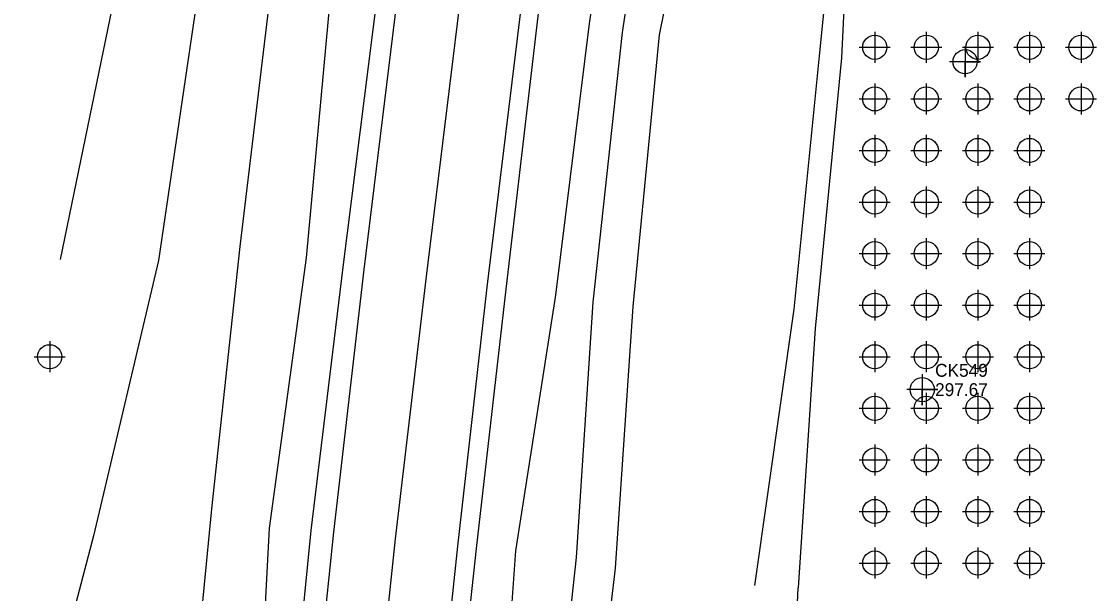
# Model space of a CAD drawing. Extents: x 1941547 to 1942851, y 663002 to 668358.
# Drawn here: x 1941924.5 to 1942133, y 668064.1 to 668175 of the extents above; entities that cross this region are included whole.
import ezdxf

# ---------------------------------------------------------------- set-up
doc = ezdxf.new("R2010")
doc.units = 0
for name, color, linetype in [('CTL GPS Vertical Cogo Elevation', 7, 'Continuous'), ('CTL NGS Vertical CELL', 7, 'Continuous'), ('Exist DTM Drainline Cogo Elevation', 7, 'Continuous'), ('Exist DTM QL2 LIDAR Elevation Point', 7, 'Continuous'), ('Exist Property Iron Pin Cogo Number', 7, 'Continuous'), ('Exist Roads EOP Cogo Point CELL', 7, 'Continuous'), ('Exist Roads EOT', 7, 'Continuous'), ('Exist Utilities Telephone UG Cable SUE LOS C Cogo Elevation', 7, 'Continuous'), ('Exist Utilities Telephone UG FO SUE LOS C Cogo Elevation', 7, 'Continuous')]:
    doc.layers.add(name, color=color, linetype=linetype)

msp = doc.modelspace()

# ---------------------------------------------------------------- linework, layer by layer
at = {"layer": 'CTL NGS Vertical CELL'}
for points in [[(1942065.04, 668323.64), (1942056.78, 668277.48), (1942048.92, 668225.34), (1942041.05, 668172.9), (1942035.33, 668120.57), (1942032.08, 668071.11), (1942028.21, 668035.32)], [(1941955.9, 668019.97), (1941956.36, 668027.93), (1941961.46, 668080.53), (1941966.93, 668131.39), (1941973.27, 668184.19), (1941981.21, 668235.19), (1941987.75, 668278.42)]]:
    msp.add_lwpolyline(points, dxfattribs=at)
at = {"layer": 'Exist DTM Drainline Cogo Elevation'}
for points in [[(1942107.52, 668170.2), (1942107.52, 668164.2), (1942107.52, 668167.2), (1942110.52, 668167.2), (1942104.52, 668167.2)], [(1942099.2, 668106.62), (1942099.2, 668100.62), (1942099.2, 668103.62), (1942102.2, 668103.62), (1942096.2, 668103.62)]]:
    msp.add_lwpolyline(points, dxfattribs=at)
for centre in [(1942107.52, 668167.2), (1942099.2, 668103.62)]:
    msp.add_circle(centre, 2.34, dxfattribs=at)
at = {"layer": 'Exist DTM QL2 LIDAR Elevation Point'}
for points in [[(1942090, 668173), (1942090, 668170)], [(1942100, 668173), (1942100, 668170)], [(1942110, 668173), (1942110, 668170)], [(1942120, 668173), (1942120, 668170)], [(1942130, 668173), (1942130, 668170)], [(1942087, 668170), (1942090, 668170)], [(1942090, 668170), (1942093, 668170)], [(1942090, 668170), (1942090, 668167)], [(1942097, 668170), (1942100, 668170)], [(1942100, 668170), (1942103, 668170)], [(1942100, 668170), (1942100, 668167)], [(1942107, 668170), (1942110, 668170)], [(1942110, 668170), (1942113, 668170)], [(1942110, 668170), (1942110, 668167)], [(1942117, 668170), (1942120, 668170)], [(1942120, 668170), (1942123, 668170)], [(1942120, 668170), (1942120, 668167)], [(1942127, 668170), (1942130, 668170)], [(1942130, 668170), (1942133, 668170)], [(1942130, 668170), (1942130, 668167)], [(1942090, 668163), (1942090, 668160)], [(1942100, 668163), (1942100, 668160)], [(1942110, 668163), (1942110, 668160)], [(1942120, 668163), (1942120, 668160)], [(1942130, 668163), (1942130, 668160)], [(1942087, 668160), (1942090, 668160)], [(1942090, 668160), (1942093, 668160)], [(1942090, 668160), (1942090, 668157)], [(1942097, 668160), (1942100, 668160)], [(1942100, 668160), (1942103, 668160)], [(1942100, 668160), (1942100, 668157)], [(1942107, 668160), (1942110, 668160)], [(1942110, 668160), (1942113, 668160)], [(1942110, 668160), (1942110, 668157)], [(1942117, 668160), (1942120, 668160)], [(1942120, 668160), (1942123, 668160)], [(1942120, 668160), (1942120, 668157)], [(1942127, 668160), (1942130, 668160)], [(1942130, 668160), (1942133, 668160)], [(1942130, 668160), (1942130, 668157)], [(1942090, 668153), (1942090, 668150)], [(1942100, 668153), (1942100, 668150)], [(1942110, 668153), (1942110, 668150)], [(1942120, 668153), (1942120, 668150)], [(1942087, 668150), (1942090, 668150)], [(1942090, 668150), (1942093, 668150)], [(1942090, 668150), (1942090, 668147)], [(1942097, 668150), (1942100, 668150)], [(1942100, 668150), (1942103, 668150)], [(1942100, 668150), (1942100, 668147)], [(1942107, 668150), (1942110, 668150)], [(1942110, 668150), (1942113, 668150)], [(1942110, 668150), (1942110, 668147)], [(1942117, 668150), (1942120, 668150)], [(1942120, 668150), (1942123, 668150)], [(1942120, 668150), (1942120, 668147)], [(1942090, 668143), (1942090, 668140)], [(1942100, 668143), (1942100, 668140)], [(1942110, 668143), (1942110, 668140)], [(1942120, 668143), (1942120, 668140)], [(1942087, 668140), (1942090, 668140)], [(1942090, 668140), (1942093, 668140)], [(1942090, 668140), (1942090, 668137)], [(1942097, 668140), (1942100, 668140)], [(1942100, 668140), (1942103, 668140)], [(1942100, 668140), (1942100, 668137)], [(1942107, 668140), (1942110, 668140)], [(1942110, 668140), (1942113, 668140)], [(1942110, 668140), (1942110, 668137)], [(1942117, 668140), (1942120, 668140)], [(1942120, 668140), (1942123, 668140)], [(1942120, 668140), (1942120, 668137)], [(1942090, 668133), (1942090, 668130)], [(1942100, 668133), (1942100, 668130)], [(1942110, 668133), (1942110, 668130)], [(1942120, 668133), (1942120, 668130)], [(1942087, 668130), (1942090, 668130)], [(1942090, 668130), (1942093, 668130)], [(1942090, 668130), (1942090, 668127)], [(1942097, 668130), (1942100, 668130)], [(1942100, 668130), (1942103, 668130)], [(1942100, 668130), (1942100, 668127)], [(1942107, 668130), (1942110, 668130)], [(1942110, 668130), (1942113, 668130)], [(1942110, 668130), (1942110, 668127)], [(1942117, 668130), (1942120, 668130)], [(1942120, 668130), (1942123, 668130)], [(1942120, 668130), (1942120, 668127)], [(1942090, 668123), (1942090, 668120)], [(1942100, 668123), (1942100, 668120)], [(1942110, 668123), (1942110, 668120)], [(1942120, 668123), (1942120, 668120)], [(1942087, 668120), (1942090, 668120)], [(1942090, 668120), (1942093, 668120)], [(1942090, 668120), (1942090, 668117)], [(1942097, 668120), (1942100, 668120)], [(1942100, 668120), (1942103, 668120)], [(1942100, 668120), (1942100, 668117)], [(1942107, 668120), (1942110, 668120)], [(1942110, 668120), (1942113, 668120)], [(1942110, 668120), (1942110, 668117)], [(1942117, 668120), (1942120, 668120)], [(1942120, 668120), (1942123, 668120)], [(1942120, 668120), (1942120, 668117)], [(1941930, 668113), (1941930, 668110)], [(1942090, 668113), (1942090, 668110)], [(1942100, 668113), (1942100, 668110)], [(1942110, 668113), (1942110, 668110)], [(1942120, 668113), (1942120, 668110)], [(1941927, 668110), (1941930, 668110)], [(1941930, 668110), (1941933, 668110)], [(1941930, 668110), (1941930, 668107)], [(1942087, 668110), (1942090, 668110)], [(1942090, 668110), (1942093, 668110)], [(1942090, 668110), (1942090, 668107)], [(1942097, 668110), (1942100, 668110)], [(1942100, 668110), (1942103, 668110)], [(1942100, 668110), (1942100, 668107)], [(1942107, 668110), (1942110, 668110)], [(1942110, 668110), (1942113, 668110)], [(1942110, 668110), (1942110, 668107)], [(1942117, 668110), (1942120, 668110)], [(1942120, 668110), (1942123, 668110)], [(1942120, 668110), (1942120, 668107)], [(1942090, 668103), (1942090, 668100)], [(1942100, 668103), (1942100, 668100)], [(1942110, 668103), (1942110, 668100)], [(1942120, 668103), (1942120, 668100)], [(1942087, 668100), (1942090, 668100)], [(1942090, 668100), (1942093, 668100)], [(1942090, 668100), (1942090, 668097)], [(1942097, 668100), (1942100, 668100)], [(1942100, 668100), (1942103, 668100)], [(1942100, 668100), (1942100, 668097)], [(1942107, 668100), (1942110, 668100)], [(1942110, 668100), (1942113, 668100)], [(1942110, 668100), (1942110, 668097)], [(1942117, 668100), (1942120, 668100)], [(1942120, 668100), (1942123, 668100)], [(1942120, 668100), (1942120, 668097)], [(1942090, 668093), (1942090, 668090)], [(1942100, 668093), (1942100, 668090)], [(1942110, 668093), (1942110, 668090)], [(1942120, 668093), (1942120, 668090)], [(1942087, 668090), (1942090, 668090)], [(1942090, 668090), (1942093, 668090)], [(1942090, 668090), (1942090, 668087)], [(1942097, 668090), (1942100, 668090)], [(1942100, 668090), (1942103, 668090)], [(1942100, 668090), (1942100, 668087)], [(1942107, 668090), (1942110, 668090)], [(1942110, 668090), (1942113, 668090)], [(1942110, 668090), (1942110, 668087)], [(1942117, 668090), (1942120, 668090)], [(1942120, 668090), (1942123, 668090)], [(1942120, 668090), (1942120, 668087)], [(1942090, 668083), (1942090, 668080)], [(1942100, 668083), (1942100, 668080)], [(1942110, 668083), (1942110, 668080)], [(1942120, 668083), (1942120, 668080)], [(1942087, 668080), (1942090, 668080)], [(1942090, 668080), (1942093, 668080)], [(1942090, 668080), (1942090, 668077)], [(1942097, 668080), (1942100, 668080)], [(1942100, 668080), (1942103, 668080)], [(1942100, 668080), (1942100, 668077)], [(1942107, 668080), (1942110, 668080)], [(1942110, 668080), (1942113, 668080)], [(1942110, 668080), (1942110, 668077)], [(1942117, 668080), (1942120, 668080)], [(1942120, 668080), (1942123, 668080)], [(1942120, 668080), (1942120, 668077)], [(1942090, 668073), (1942090, 668070)], [(1942100, 668073), (1942100, 668070)], [(1942110, 668073), (1942110, 668070)], [(1942120, 668073), (1942120, 668070)], [(1942087, 668070), (1942090, 668070)], [(1942090, 668070), (1942093, 668070)], [(1942090, 668070), (1942090, 668067)], [(1942097, 668070), (1942100, 668070)], [(1942100, 668070), (1942103, 668070)], [(1942100, 668070), (1942100, 668067)], [(1942107, 668070), (1942110, 668070)], [(1942110, 668070), (1942113, 668070)], [(1942110, 668070), (1942110, 668067)], [(1942117, 668070), (1942120, 668070)], [(1942120, 668070), (1942123, 668070)], [(1942120, 668070), (1942120, 668067)]]:
    msp.add_lwpolyline(points, dxfattribs=at)
for centre in [(1942090, 668170), (1942100, 668170), (1942110, 668170), (1942120, 668170), (1942130, 668170), (1942090, 668160), (1942100, 668160), (1942110, 668160), (1942120, 668160), (1942130, 668160), (1942090, 668150), (1942100, 668150), (1942110, 668150), (1942120, 668150), (1942090, 668140), (1942100, 668140), (1942110, 668140), (1942120, 668140), (1942090, 668130), (1942100, 668130), (1942110, 668130), (1942120, 668130), (1942090, 668120), (1942100, 668120), (1942110, 668120), (1942120, 668120), (1941930, 668110), (1942090, 668110), (1942100, 668110), (1942110, 668110), (1942120, 668110), (1942090, 668100), (1942100, 668100), (1942110, 668100), (1942120, 668100), (1942090, 668090), (1942100, 668090), (1942110, 668090), (1942120, 668090), (1942090, 668080), (1942100, 668080), (1942110, 668080), (1942120, 668080), (1942090, 668070), (1942100, 668070), (1942110, 668070), (1942120, 668070)]:
    msp.add_circle(centre, 2.34, dxfattribs=at)
at = {"layer": 'Exist Property Iron Pin Cogo Number'}
msp.add_lwpolyline([(1942029.46, 668331.31), (1942023.01, 668282.84), (1942016.05, 668230.03), (1942009.43, 668177.78), (1942002.96, 668125.07), (1941997.02, 668074.7), (1941991.66, 668023.79), (1941986.94, 667972.46)], dxfattribs=at)
at = {"layer": 'Exist Roads EOT'}
for points in [[(1941974.94, 667973.32), (1941979.78, 668024.95), (1941985.13, 668076.01), (1941991.01, 668126.92), (1941997.4, 668179.23), (1942004.19, 668231.52), (1942010.99, 668284.5), (1942017.64, 668332.73)], [(1942041.27, 668329.74), (1942034.74, 668281.46), (1942027.82, 668228.76), (1942021.25, 668176.51), (1942014.78, 668123.52), (1942009.06, 668073.27), (1942003.75, 668022.48), (1941998.95, 667971.48)]]:
    msp.add_lwpolyline(points, dxfattribs=at)
at = {"layer": 'Exist Utilities Telephone UG Cable SUE LOS C Cogo Elevation'}
for points in [[(1941971.03, 667973.65), (1941975.67, 668025.36), (1941980.69, 668076.34), (1941986.93, 668127.4), (1941993.5, 668179.65), (1942000.09, 668231.99), (1942007.07, 668285.02), (1942013.37, 668333.1)], [(1942044.81, 668329.3), (1942038.47, 668280.9), (1942031.51, 668228.32), (1942024.64, 668176.05), (1942018.45, 668123.08), (1942012.73, 668072.84), (1942007.21, 668022.09), (1942002.64, 667971.13)]]:
    msp.add_lwpolyline(points, dxfattribs=at)
at = {"layer": 'Exist Utilities Telephone UG FO SUE LOS C Cogo Elevation'}
msp.add_line((1942073.81, 668032.13), (1942075.14, 668065.2), dxfattribs=at)
for points in [[(1941962.13, 668340.29), (1941957.49, 668289.01), (1941947.2, 668235.57), (1941944.34, 668188.52), (1941932.04, 668128.88)], [(1941979.33, 668336.88), (1941973.16, 668290.22), (1941957.68, 668233.23), (1941959.05, 668182.66), (1941951.08, 668128.66), (1941938.48, 668075.27), (1941926.68, 668030.16), (1941923.98, 667997.07), (1941921.59, 667975.09)], [(1941963.56, 667974.26), (1941969.96, 668026.4), (1941972.62, 668076.75), (1941979.78, 668129.2), (1941984.51, 668180.47), (1941993.7, 668233.8), (1941997.18, 668286.06), (1942002.92, 668333.88)], [(1942056.67, 668329.33), (1942047.84, 668279.94), (1942042.39, 668225.95), (1942034.64, 668174.64), (1942028.12, 668121.92), (1942020.36, 668072.35), (1942016.58, 668019.92), (1942012.22, 667970.41)], [(1942078.88, 668326.6), (1942067.77, 668277.54), (1942058.52, 668223.54), (1942048.2, 668172.4), (1942043.07, 668119.76), (1942039.64, 668069.04), (1942033.78, 668019.22), (1942028.79, 667968.01)], [(1942101.25, 668325.69), (1942094.52, 668272.27), (1942086.32, 668225.72), (1942083.54, 668167.95), (1942078.43, 668115.46), (1942075.14, 668065.2)], [(1942066.74, 668065.64), (1942074.37, 668119.2), (1942079.27, 668168.35), (1942084.17, 668217.09), (1942091.04, 668273.05), (1942094.11, 668302.73)]]:
    msp.add_lwpolyline(points, dxfattribs=at)

# ---------------------------------------------------------------- texts
at = {"layer": 'CTL GPS Vertical Cogo Elevation'}
msp.add_text('CK549', height=2.5, dxfattribs=at).set_placement((1942101.7, 668106.12))
at = {"layer": 'Exist Roads EOP Cogo Point CELL'}
msp.add_text('297.67', height=2.5, dxfattribs=at).set_placement((1942101.7, 668102.37))

doc.saveas('drawing.dxf')
